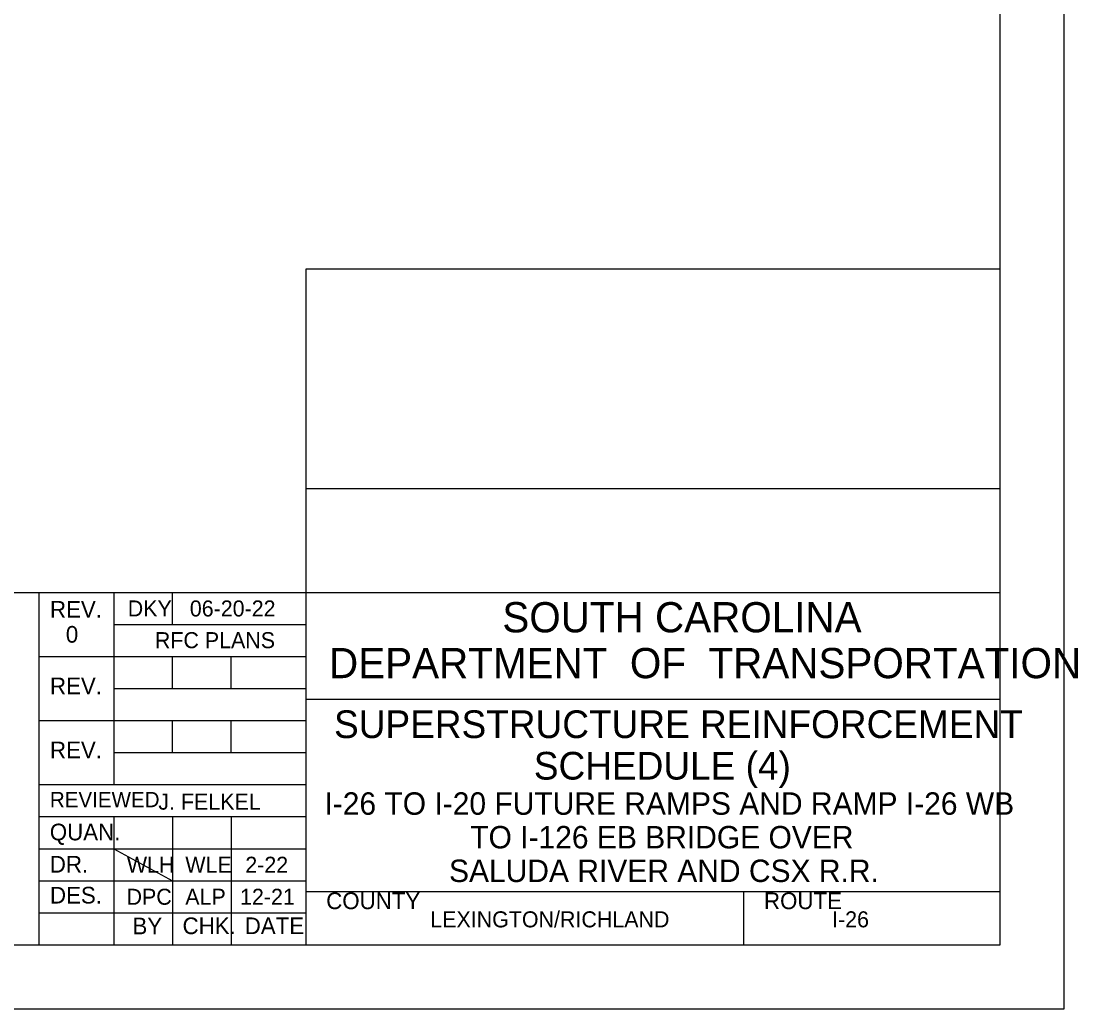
# Model space of a CAD drawing. Extents: x -133.1 to -97, y -1.7 to 20.6.
# Drawn here: x -105.28 to -97.03, y -1.69 to 6.02 of the extents above; entities that cross this region are included whole.
import ezdxf

# ---------------------------------------------------------------- set-up
doc = ezdxf.new("R2010")
doc.units = 0
for name, color, linetype in [('BR_BORDER LINES', 7, 'Continuous'), ('BR_TEXT', 7, 'Continuous'), ('Level 31', 7, 'Continuous')]:
    doc.layers.add(name, color=color, linetype=linetype)

msp = doc.modelspace()

# ---------------------------------------------------------------- linework, layer by layer
at = {"layer": 'BR_BORDER LINES'}
for p, q in [((-97.6416, -1.191), (-97.6416, 19.8089)), ((-103.0585, -1.191), (-103.0585, 4.0855)), ((-103.0585, 4.0855), (-97.6416, 4.0855)), ((-103.0583, 2.3708), (-97.6416, 2.3708)), ((-110.5071, 1.5591), (-105.1419, 1.5591)), ((-105.1419, -1.191), (-105.1419, 1.5591)), ((-105.1419, 1.5591), (-97.6416, 1.5591)), ((-104.5585, 1.5591), (-104.5585, 0.059)), ((-104.1002, 1.3091), (-104.1002, 1.5591)), ((-104.5585, 1.3091), (-103.0585, 1.3091)), ((-105.1419, 1.0591), (-103.0585, 1.0591)), ((-104.1002, 0.809), (-104.1002, 1.0591)), ((-103.6418, 0.809), (-103.6418, 1.0591)), ((-104.5585, 0.809), (-103.0585, 0.809)), ((-103.0585, 0.7257), (-103.0585, 0.7257)), ((-103.0585, 0.7257), (-97.6414, 0.7257)), ((-105.1419, 0.559), (-103.0585, 0.559)), ((-104.1002, 0.309), (-104.1002, 0.559)), ((-103.6418, 0.309), (-103.6418, 0.559)), ((-104.5585, 0.309), (-103.0585, 0.309)), ((-105.1419, 0.059), (-103.0585, 0.059)), ((-105.1419, -0.191), (-103.0585, -0.191)), ((-104.5585, -0.191), (-104.5585, -1.191)), ((-104.1002, -0.191), (-104.1002, -1.191)), ((-103.6418, -0.191), (-103.6418, -1.191)), ((-105.1419, -0.441), (-103.0585, -0.441)), ((-105.1419, -0.691), (-103.0585, -0.691)), ((-103.0585, -0.7744), (-97.6416, -0.7744)), ((-102.9609, -0.7744), (-97.6416, -0.7744)), ((-99.6417, -1.191), (-99.6417, -0.7744)), ((-105.1419, -0.941), (-103.0585, -0.941)), ((-131.3076, -1.191), (-97.6416, -1.191))]:
    msp.add_line(p, q, dxfattribs=at)
at = {"layer": 'Level 31'}
for p, q in [((-100.3498, 0.2855), (-100.3498, 0.2855)), ((-104.5585, -0.441), (-104.1002, -0.691))]:
    msp.add_line(p, q, dxfattribs=at)
msp.add_lwpolyline([(-133.1409, -1.691), (-97.141, -1.691), (-97.141, 20.309), (-133.1409, 20.309)], close=True, dxfattribs=at)

# ---------------------------------------------------------------- texts
at = {"layer": 'BR_TEXT'}
for s, height, p in [('REV.', 0.13001, (-105.0572, 1.362)), ('DKY', 0.12499, (-104.4502, 1.3715)), ('06-20-22', 0.12499, (-103.9658, 1.3715)), ('SOUTH CAROLINA', 0.23587, (-101.5266, 1.2475)), ('0', 0.13, (-104.9333, 1.167)), ('RFC PLANS', 0.12499, (-104.2386, 1.124)), ('DEPARTMENT  OF  TRANSPORTATION', 0.23587, (-102.8793, 0.8897)), ('REV.', 0.13001, (-105.0572, 0.7645)), ('SUPERSTRUCTURE REINFORCEMENT', 0.216, (-102.84, 0.4225)), ('REV.', 0.13001, (-105.0572, 0.2644)), ('SCHEDULE (4)', 0.216, (-101.2806, 0.0985)), ('REVIEWED', 0.12, (-105.0579, -0.1175)), ('I-26 TO I-20 FUTURE RAMPS AND RAMP I-26 WB', 0.175, (-102.915, -0.1761)), ('J. FELKEL', 0.125, (-104.2114, -0.1366)), ('QUAN.', 0.13001, (-105.0585, -0.3758)), ('TO I-126 EB BRIDGE OVER', 0.175, (-101.777, -0.4386)), ('DR.', 0.13001, (-105.0583, -0.6274)), ('WLH', 0.12499, (-104.4571, -0.6286)), ('WLE', 0.12499, (-104.0008, -0.6286)), ('2-22', 0.12499, (-103.5328, -0.6286)), ('SALUDA RIVER AND CSX R.R.', 0.175, (-101.9427, -0.7011)), ('DES.', 0.13001, (-105.0572, -0.8687)), ('DPC', 0.12499, (-104.4595, -0.8786)), ('ALP', 0.12499, (-104.0012, -0.8786)), ('12-21', 0.12499, (-103.5737, -0.8786)), ('COUNTY', 0.13001, (-102.9012, -0.9127)), ('ROUTE', 0.13001, (-99.4844, -0.9127)), ('BY', 0.13001, (-104.4132, -1.109)), ('CHK.', 0.13001, (-104.0224, -1.1077)), ('DATE', 0.13001, (-103.5372, -1.1076)), ('LEXINGTON/RICHLAND', 0.124995, (-102.089, -1.0548)), ('I-26', 0.12499, (-98.953, -1.0548))]:
    msp.add_text(s, height=height, dxfattribs=at).set_placement(p)

doc.saveas('drawing.dxf')
